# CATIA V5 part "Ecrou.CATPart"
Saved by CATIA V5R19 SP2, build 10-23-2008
Part number: Ecrou
Bounding box of the stored display mesh (mm): x -5.196 to 5.196, y -4.5 to 4.5, z -2 to 2
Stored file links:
  F:\Projet CAO\pièces et assemblages\mécanisme 577\577-SaintAime\577-SaintAime\Ecrou.CATPart
  C:\Program Files\Dassault Systemes\B19\win_b64\reffiles\standard\MetricThickPitch.txt
  C:\Program Files\Dassault Systemes\B19\win_b64\reffiles\standard\MetricThinPitch.txt
  F:\Projet CAO\pièces et assemblages\mécanisme 577\577-SaintAime\577-SaintAime\mecanisme577_parametre.CATProduct
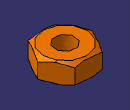
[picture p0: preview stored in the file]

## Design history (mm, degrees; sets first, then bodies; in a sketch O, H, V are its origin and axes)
External parameters (linked from other documents)
  External.diam_trou_de_passage = 4 mm
Body1 (main body)
  Sketch1 on xy-plane, origin (0, 0, 0), H (1, 0, 0), V (0, 1, 0)
    point P1 (5.1962, 0)
    point P2 (2.5981, 4.5)
    point P3 (-2.5981, 4.5)
    point P4 (-5.1962, 0)
    point P5 (-2.5981, -4.5)
    point P6 (2.5981, -4.5)
    point P7 (3.8971, 2.25)
    line L1 (5.1962, 0) -> (2.5981, 4.5)
    line L2 (2.5981, 4.5) -> (-2.5981, 4.5)
    line L3 (-2.5981, 4.5) -> (-5.1962, 0)
    line L4 (-5.1962, 0) -> (-2.5981, -4.5)
    line L5 (-2.5981, -4.5) -> (2.5981, -4.5)
    line L6 (2.5981, -4.5) -> (5.1962, 0)
    construction line L7 (0, 0) -> (3.8971, 2.25)
    construction circle A1 centre (0, 0) radius 5.1962
    construction arc A2 centre (-2.5981, -4.5) radius 5.1962 from (-5.1962, 0) to (2.5981, -4.5) cw
    construction arc A3 centre (2.5981, 4.5) radius 5.1962 from (-2.5981, 4.5) to (5.1962, 0) ccw
    axis line L8 (-26.2747, 0) -> (18.9581, 0)
    distance L2 L5 = 9 {= (External.diam_trou_de_passage /2) + 7 mm}
    coincidence: A1 P1, A1 P2, A1 P3, A1 P4, A1 P5, A1 P6, A2 O, A3 O, L8 P1, P4 L8
    midpoint: P7 L1
    parallelism: L1 L4
    horizontal: L8 H
  Pad1: profile Sketch1, direction (0, 0, 1), length 2, mirrored extent
  Body2
    Sketch2 on zx-plane, origin (0, 0, 0), H (-1, 0, 0), V (0, 0, 1)
      line L1 (4.1962, 2) -> (5.1962, 2)
      line L2 (5.1962, 2) -> (5.1962, 1.4226)
      line L3 (5.1962, 1.4226) -> (4.1962, 2)
      reference projected line E1 (5.1962, -4.2) -> (5.1962, 4.2) from edge [face of Pad1 from Sketch1.L4 | face of Pad1 from Sketch1.L3]
      reference projected line E2 (4.6188, 2) -> (9.2376, 2) from edge [face of Pad1 from Sketch1.L3 | end face of Pad1]
      angle L3 L1 = 30
      length L1 = 1
      horizontal: L1 H
      vertical: L2 V
      coincidence: L2 E1, L1 E2
    Shaft1: profile Sketch2, axis Sketch2.V, angle 360
    Mirror1: of Shaft1, Sketch2, about xy-plane
  Remove1: tool Body2
  Sketch3 on end face of Pad1, origin (1.9425, -2.7682, 2), H (1, 0, 0), V (0, 1, 0)
    point P1 (-1.9425, 2.7682)
  Hole1: placed by Sketch3, at (0, 0, 2) direction (0, 0, -1), diameter 4 {= External.diam_trou_de_passage}, depth 10
Relations
  Hole1.DiameterThread = External.diam_trou_de_passage - 1 mm (deactivated)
